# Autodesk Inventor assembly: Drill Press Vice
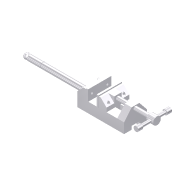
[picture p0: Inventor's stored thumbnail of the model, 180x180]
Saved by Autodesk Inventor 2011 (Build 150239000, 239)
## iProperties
Shininess: 64.0
Length Units: 11269
Angle Units: 11279
Time Units: 11290
Mass Units: 11283
Length Display Precision: 3
Angle Display Precision: 2
Created: 2002-02
Part Number: Drill Press Vice
Document SubType Name: Assembly
Designer: ***
Density: 0.0
Volumn: 0.0
Area: 0.0
PropertySet Name: Model Information
Control State: 0
Master: False
Checked Out: False
Author: ***
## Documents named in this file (9)
- C:\Users\CADSoft\Desktop\part files\c13-inv-2011-prt\c13-tut02-inv\Drill Press Vice.iam
- C:\Inventor_2011\tutorials\c13\Drill Press Vice\Base.ipt
- C:\Inventor_2011\tutorials\c13\Drill Press Vice\Movable Jaw.ipt
- C:\Inventor_2011\tutorials\c13\Drill Press Vice\Jaw Face.ipt
- C:\Inventor_2011\tutorials\c13\Drill Press Vice\Clamp Screw.ipt
- C:\Inventor_2011\tutorials\c13\Drill Press Vice\Clamp Screw Handle.ipt
- C:\Inventor_2011\tutorials\c13\Drill Press Vice\Handle Stop.ipt
- C:\Inventor_2011\tutorials\c13\Drill Press Vice\Cap Screw.ipt
- C:\Inventor_2011\tutorials\c13\Drill Press Vice\Safety Handle.ipt
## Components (13 placed, 8 different names)
1. Base:1 — Insert:1, Insert:2, Insert:3, Angle:1, Angle:3, Insert:10, Insert:11, Insert:12
2. Movable Jaw:1 — Insert:1, Insert:2, Insert:4, Angle:2, Insert:5, Insert:8, Insert:9
3. Jaw Face:1 — Insert:4, Angle:2
4. Jaw Face:2 — Insert:3, Angle:1
5. Clamp Screw:1 — Insert:5, Angle:3, Mate:1, Mate:2
6. Clamp Screw Handle:1 — Mate:1, Mate:2, Insert:6, Insert:7
7. Handle Stop:1 — Insert:6
8. Handle Stop:2 — Insert:7
9. Cap Screw:1 — Insert:9
10. Cap Screw:2 — Insert:8
11. Cap Screw:4 — Insert:10
12. Cap Screw:5 — Insert:11
13. Safety Handle:1 — Insert:12
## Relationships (17: Insert 12, Angle 3, Mate 2)
- Insert:1: Base:1 ↔ Movable Jaw:1
- Insert:2: Base:1 ↔ Movable Jaw:1
- Insert:3: Base:1 ↔ Jaw Face:2
- Angle:1: Base:1 ↔ Jaw Face:2
- Insert:4: Movable Jaw:1 ↔ Jaw Face:1
- Angle:2: Movable Jaw:1 ↔ Jaw Face:1
- Insert:5: Movable Jaw:1 ↔ Clamp Screw:1
- Angle:3: Base:1 ↔ Clamp Screw:1
- Mate:1: Clamp Screw:1 ↔ Clamp Screw Handle:1
- Mate:2: Clamp Screw:1 ↔ Clamp Screw Handle:1
- Insert:6: Clamp Screw Handle:1 ↔ Handle Stop:1
- Insert:7: Clamp Screw Handle:1 ↔ Handle Stop:2
- Insert:8: Movable Jaw:1 ↔ Cap Screw:2
- Insert:9: Movable Jaw:1 ↔ Cap Screw:1
- Insert:10: Base:1 ↔ Cap Screw:4
- Insert:11: Base:1 ↔ Cap Screw:5
- Insert:12: Base:1 ↔ Safety Handle:1
